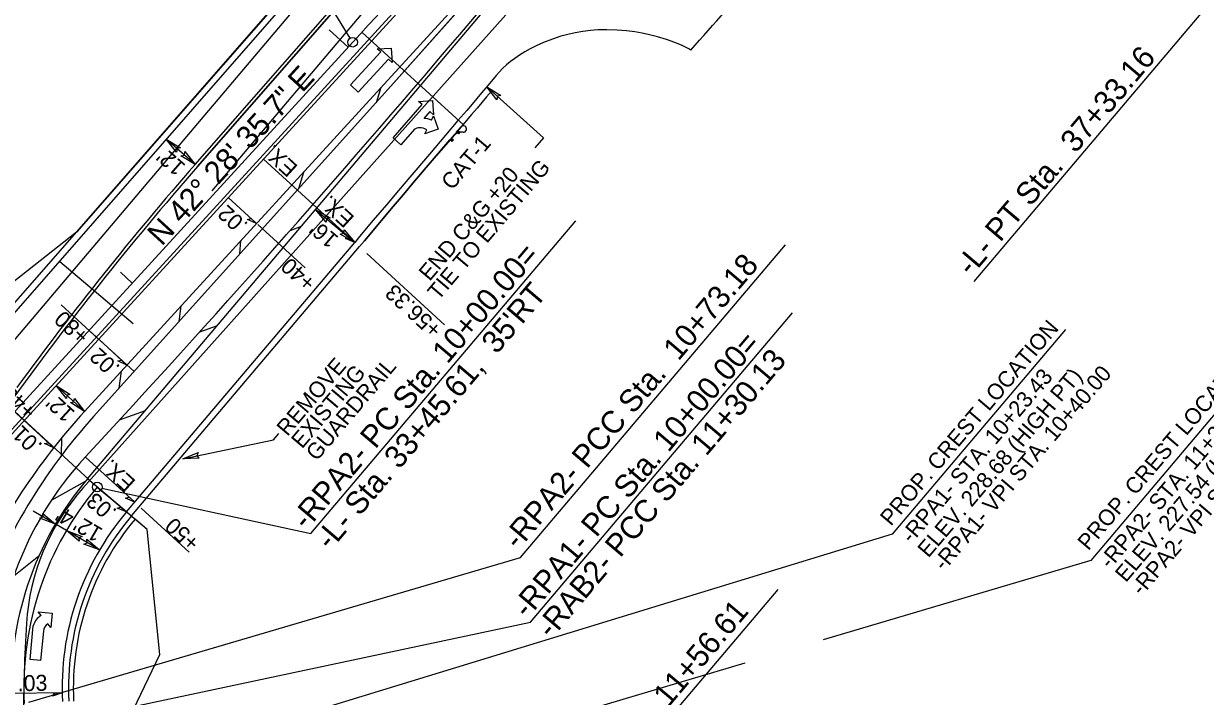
# Model space of a CAD drawing. Extents: x 1761082 to 1764358, y 421907 to 425434.
# Drawn here: x 1762805.2 to 1763174.6, y 423617.8 to 423828.1 of the extents above; entities that cross this region are included whole.
import ezdxf

# ---------------------------------------------------------------- set-up
doc = ezdxf.new("R2010")
doc.units = 0
for name, color, linetype in [('MARK HOOKS CENTER LEFT TURN ARROW CELL', 7, 'Continuous'), ('MARK HOOKS CENTER STRAIGHT LEFT TURN ARROW CELL', 7, 'Continuous'), ('MARK LEFT TURN ARROW CELL', 7, 'Continuous'), ('MARK STRAIGHT RIGHT ARROW CELL', 7, 'Continuous'), ('MARK UTURN ARROW CELL', 7, 'Continuous'), ('Prop Geotechnical Rock Plating', 7, 'Continuous'), ('Prop Horizontal Alignment Tick Large', 7, 'Continuous'), ('Prop Mkg 3ft Min Skp 3ft Wide White', 7, 'Continuous'), ('Prop Mkg 3ft Min Skp 9ft Wide White', 7, 'Continuous'), ('Prop Mkg Min Skp 6ft Yellow', 7, 'Continuous'), ('Prop Mkg Skp Wht', 7, 'Continuous'), ('Prop Mkg Solid White Diagonals', 7, 'Continuous'), ('Prop Mkg Solid White Edge Line', 7, 'Continuous'), ('Prop Mkg Solid White Lane Line', 7, 'Continuous'), ('Prop Mkg Solid White Multiple Diagonals V8i', 7, 'Continuous'), ('Prop Mkg Solid Yel Skip LT', 7, 'Continuous'), ('Prop Mkg Solid Yel Skip RT', 7, 'Continuous'), ('Prop Mkg Solid Yellow Diagonals', 7, 'Continuous'), ('Prop Mkg Solid Yellow Lane Line', 7, 'Continuous'), ('Prop Mkg Yld Lin', 7, 'Continuous'), ('Scratch_Level_0', 7, 'Continuous'), ('Scratch_Level_1', 7, 'Continuous'), ('Scratch_Level_5', 7, 'Continuous')]:
    doc.layers.add(name, color=color, linetype=linetype)

msp = doc.modelspace()

# ---------------------------------------------------------------- linework, layer by layer
at = {"layer": 'MARK HOOKS CENTER STRAIGHT LEFT TURN ARROW CELL'}
msp.add_line((1762839.12, 423747.01), (1762835.44, 423750.39), dxfattribs=at)
at = {"layer": 'MARK LEFT TURN ARROW CELL'}
for p, q in [((1762783.77, 423719.57), (1762897.35, 423849.4)), ((1762951.44, 423807.05), (1762949.96, 423808.4)), ((1762838.89, 423674.21), (1762910.22, 423758.4))]:
    msp.add_line(p, q, dxfattribs=at)
msp.add_lwpolyline([(1762951.44, 423807.05), (1762949.87, 423805.19), (1762948.4, 423803.44), (1762946.93, 423801.7), (1762945.23, 423799.7), (1762942.5, 423796.49), (1762938.59, 423791.92), (1762933.56, 423786.04), (1762927.4, 423778.84), (1762923.9, 423774.7), (1762920.11, 423770.21), (1762916.03, 423765.34), (1762911.78, 423760.26), (1762910.22, 423758.4)], dxfattribs=at)
msp.add_arc((1762902.22, 423620.56), 83, 139.7301, 182.9577, dxfattribs=at)
at = {"layer": 'MARK STRAIGHT RIGHT ARROW CELL'}
msp.add_line((1762908.06, 423822.3), (1762796.93, 423700.93), dxfattribs=at)
for centre, radius, start, end in [((1758482.74, 427874.03), 6000, 317.523415, 319.730103), ((1762902.22, 423620.56), 97, 139.7301, 182.9577)]:
    msp.add_arc(centre, radius, start, end, dxfattribs=at)
at = {"layer": 'MARK UTURN ARROW CELL'}
for points in [[(1762907.27, 423823.58), (1762843.21, 423928.07), (1762914.03, 424011.67)], [(1763061.63, 423994.46), (1763173.2, 423831.29), (1763102.23, 423747.51)], [(1762829.68, 423682.94), (1762895, 423668.7), (1762977.8, 423766.44)], [(1762806.79, 423615.98), (1762960.53, 423661.22), (1763043.33, 423758.96)], [(1762782.05, 423602.47), (1762963.66, 423641.02), (1763045.54, 423737.66)], [(1762831.94, 423537.15), (1762958.32, 423553.44), (1763041.12, 423651.17)]]:
    msp.add_lwpolyline(points, dxfattribs=at)
for centre in [(1762908.06, 423822.3), (1762828.21, 423683.26)]:
    msp.add_circle(centre, 1.5, dxfattribs=at)
at = {"layer": 'Prop Geotechnical Rock Plating'}
msp.add_line((1762843.83, 423670.03), (1762840.04, 423673.24), dxfattribs=at)
msp.add_lwpolyline([(1762852.54, 423557.42), (1762830, 423593.66), (1762847.81, 423630.88), (1762843.83, 423670.03)], dxfattribs=at)
msp.add_arc((1762902.22, 423620.56), 81.5, 139.7301, 182.9577, dxfattribs=at)
at = {"layer": 'Prop Horizontal Alignment Tick Large'}
for p, q in [((1762906.65, 423820.76), (1762900.75, 423826.17)), ((1762828.21, 423683.26), (1762834.32, 423678.09))]:
    msp.add_line(p, q, dxfattribs=at)
at = {"layer": 'Prop Mkg 3ft Min Skp 3ft Wide White'}
msp.add_line((1762796.93, 423700.93), (1762908.06, 423822.3), dxfattribs=at)
for centre, radius, start, end in [((1758482.74, 427874.03), 6000, 317.523415, 319.730103), ((1762902.22, 423620.56), 97, 139.7301, 182.9577)]:
    msp.add_arc(centre, radius, start, end, dxfattribs=at)
at = {"layer": 'Prop Mkg 3ft Min Skp 9ft Wide White'}
for p, q in [((1762897.35, 423849.4), (1762821.72, 423762.95)), ((1762821.72, 423762.95), (1762765.85, 423719.03)), ((1762838.89, 423674.21), (1762910.21, 423758.4))]:
    msp.add_line(p, q, dxfattribs=at)
msp.add_lwpolyline([(1762910.22, 423758.41), (1762911.78, 423760.26), (1762916.03, 423765.34), (1762920.11, 423770.21), (1762923.9, 423774.7), (1762927.4, 423778.84), (1762933.56, 423786.04), (1762938.48, 423791.8)], dxfattribs=at)
msp.add_arc((1762902.22, 423620.56), 83, 139.7301, 182.9577, dxfattribs=at)
at = {"layer": 'Prop Mkg Skp Wht'}
for p, q in [((1762785.28, 423718.25), (1762898.9, 423848.13)), ((1762837.37, 423675.5), (1762908.69, 423759.69))]:
    msp.add_line(p, q, dxfattribs=at)
msp.add_lwpolyline([(1763013.76, 423819.86), (1763013.17, 423820.21), (1763011.04, 423821.27), (1763008.75, 423822.22), (1763006.17, 423823.13), (1763003.38, 423823.97), (1763000.85, 423824.64), (1762998.6, 423825.13), (1762996.23, 423825.54), (1762993.64, 423825.86), (1762990.71, 423826.08), (1762987.53, 423826.18), (1762984.74, 423826.13), (1762982.39, 423825.92), (1762980.02, 423825.62), (1762977.58, 423825.22), (1762975.29, 423824.74), (1762973.11, 423824.15), (1762970.56, 423823.29), (1762967.71, 423822.18), (1762965.37, 423821.16), (1762963.58, 423820.25), (1762961.88, 423819.29), (1762960.22, 423818.26), (1762958.72, 423817.26), (1762957.39, 423816.27), (1762956.16, 423815.27), (1762954.9, 423814.1), (1762952.96, 423811.95), (1762950.4, 423808.93), (1762948.34, 423806.48), (1762946.87, 423804.73), (1762945.4, 423802.99), (1762943.71, 423801), (1762940.97, 423797.79), (1762937.07, 423793.22), (1762932.04, 423787.34), (1762925.88, 423780.14), (1762922.37, 423776), (1762918.58, 423771.49), (1762914.5, 423766.63), (1762910.24, 423761.55), (1762908.69, 423759.69)], dxfattribs=at)
for centre, radius, start, end in [((1758482.74, 427874.03), 6080, 318.179172, 318.487231), ((1762902.22, 423620.56), 85, 139.7301, 182.9577)]:
    msp.add_arc(centre, radius, start, end, dxfattribs=at)
at = {"layer": 'Prop Mkg Solid White Diagonals'}
for p, q in [((1763090.51, 424047.41), (1762859.56, 423783.42)), ((1762783.48, 423681.64), (1763081.76, 424007.42)), ((1762974.97, 423870.42), (1762920.01, 423808.54)), ((1762941.52, 423824.75), (1762977.99, 423867.8)), ((1762920.01, 423808.54), (1762827.08, 423705.32))]:
    msp.add_line(p, q, dxfattribs=at)
for centre, radius, start, end in [((1759889.49, 426410.3), 4000, 317.20084, 319.7301), ((1763611.44, 423125.64), 999, 138.81963, 144.27858), ((1762960.85, 423584.88), 180, 138.0009, 160.0358), ((1762902.22, 423620.56), 106, 137.2008, 182.9577)]:
    msp.add_arc(centre, radius, start, end, dxfattribs=at)
at = {"layer": 'Prop Mkg Solid White Edge Line'}
msp.add_line((1762864.1, 423775.9), (1762984.04, 423917.48), dxfattribs=at)
at = {"layer": 'Prop Mkg Solid White Lane Line'}
for p, q in [((1762859.56, 423783.42), (1763090.51, 424047.41)), ((1762783.48, 423681.64), (1763081.76, 424007.42)), ((1762920.01, 423808.54), (1762974.97, 423870.42)), ((1762941.52, 423824.75), (1762977.99, 423867.8)), ((1762827.08, 423705.32), (1762920.01, 423808.54))]:
    msp.add_line(p, q, dxfattribs=at)
for centre, radius, start, end in [((1759889.49, 426410.3), 4000, 317.20084, 319.7301), ((1763611.44, 423125.64), 999, 138.81963, 144.27858), ((1762960.85, 423584.88), 180, 138.0009, 160.0358), ((1762902.22, 423620.56), 106, 137.2008, 182.9577)]:
    msp.add_arc(centre, radius, start, end, dxfattribs=at)
at = {"layer": 'Prop Mkg Solid White Multiple Diagonals V8i'}
for p, q in [((1762816.51, 423753.76), (1762839.4, 423734.37)), ((1762839.71, 423719.36), (1762825.62, 423732.26)), ((1762828.21, 423683.26), (1762802.4, 423706.9)), ((1762843.83, 423670.03), (1762828.21, 423683.26))]:
    msp.add_line(p, q, dxfattribs=at)
at = {"layer": 'Prop Mkg Solid Yel Skip RT'}
for p, q in [((1762858.8, 423784.07), (1762849.77, 423791.98)), ((1762896.48, 423770.03), (1762908.69, 423759.69)), ((1762878.4, 423765.29), (1762893.16, 423751.77)), ((1762936.74, 423734), (1762912.47, 423756.23)), ((1762816.89, 423740.25), (1762828.5, 423729.62)), ((1762789.35, 423718.63), (1762805.32, 423704.01)), ((1762815.37, 423714.98), (1762824.22, 423706.88)), ((1762818.56, 423669.65), (1762808.21, 423675.72)), ((1762856.95, 423662.9), (1762841.96, 423676.62)), ((1762828.91, 423663.57), (1762818.56, 423669.65))]:
    msp.add_line(p, q, dxfattribs=at)
for points in [[(1762949.96, 423808.4), (1762967.72, 423792.43), (1762965.05, 423789.27)], [(1762854.91, 423692.06), (1762883.31, 423697.99), (1762884.97, 423699.95)]]:
    msp.add_lwpolyline(points, dxfattribs=at)
at = {"layer": 'Prop Mkg Solid Yellow Diagonals'}
for p, q in [((1762915.73, 423820.26), (1762920.14, 423820.48)), ((1762916.83, 423819.25), (1762915.73, 423820.26)), ((1762920.14, 423820.48), (1762920.37, 423816)), ((1762907.36, 423808.94), (1762916.83, 423819.25)), ((1762919.26, 423817.02), (1762909.79, 423806.71)), ((1762920.37, 423816), (1762919.26, 423817.02)), ((1762909.79, 423806.71), (1762907.36, 423808.94)), ((1762920.67, 423792.39), (1762929.73, 423802.8)), ((1762928.6, 423803.78), (1762933.01, 423804.06)), ((1762929.73, 423802.8), (1762928.6, 423803.78)), ((1762933.01, 423804.06), (1762933.35, 423799.65)), ((1762932.22, 423800.63), (1762930.35, 423798.48)), ((1762933.35, 423799.65), (1762932.22, 423800.63)), ((1762932.66, 423797.94), (1762933.31, 423799.29)), ((1762933.31, 423799.29), (1762934.77, 423795.11)), ((1762927.4, 423795.09), (1762923.16, 423790.22)), ((1762934.77, 423795.11), (1762930.58, 423793.64)), ((1762930.58, 423793.64), (1762931.2, 423794.96)), ((1762923.16, 423790.22), (1762920.67, 423792.39)), ((1762810.65, 423643.1), (1762809.71, 423644.24)), ((1762809.71, 423644.24), (1762814.09, 423643.86)), ((1762814.09, 423643.86), (1762813.7, 423639.38)), ((1762807.18, 423629.37), (1762808.22, 423639.87)), ((1762813.7, 423639.38), (1762812.75, 423640.52)), ((1762811.36, 423638.15), (1762810.46, 423629.05)), ((1762810.46, 423629.05), (1762807.18, 423629.37))]:
    msp.add_line(p, q, dxfattribs=at)
for centre, radius, start, end in [((1762930.47, 423794.06), 4.43, 60.5808, 91.4594), ((1762928.82, 423793), 2.52, 88.0631, 124.3751), ((1762929.03, 423791.09), 4.43, 60.6996, 91.5532), ((1762813.29, 423638.57), 5.25, 120.3493, 165.661), ((1762814.61, 423637.84), 3.27, 124.6789, 174.3371)]:
    msp.add_arc(centre, radius, start, end, dxfattribs=at)
at = {"layer": 'Prop Mkg Solid Yellow Lane Line'}
for points in [[(1762953.16, 423804.33), (1762949.96, 423808.4), (1762954.38, 423805.64), (1762953.29, 423805.4)], [(1762853.03, 423787.95), (1762849.77, 423791.98), (1762854.23, 423789.28), (1762853.14, 423789.03)], [(1762855.54, 423788.1), (1762858.8, 423784.07), (1762854.34, 423786.77), (1762855.43, 423787.02)], [(1762899.81, 423766.06), (1762896.48, 423770.03), (1762900.98, 423767.41), (1762899.9, 423767.14)], [(1762905.36, 423763.66), (1762908.69, 423759.69), (1762904.19, 423762.32), (1762905.27, 423762.59)], [(1762818.54, 423710.88), (1762815.37, 423714.98), (1762819.76, 423712.18), (1762818.67, 423711.95)], [(1762821.05, 423710.97), (1762824.22, 423706.88), (1762819.82, 423709.67), (1762820.91, 423709.9)], [(1762860.08, 423692.25), (1762854.91, 423692.06), (1762859.75, 423694), (1762859.29, 423692.98)], [(1762811.15, 423675.01), (1762815.11, 423671.67), (1762810.23, 423673.49), (1762811.25, 423673.94)], [(1762822.52, 423666.31), (1762818.56, 423669.65), (1762823.45, 423667.83), (1762822.42, 423667.38)], [(1762824.95, 423666.91), (1762828.91, 423663.57), (1762824.03, 423665.39), (1762825.05, 423665.84)]]:
    msp.add_lwpolyline(points, close=True, dxfattribs=at)
at = {"layer": 'Prop Mkg Yld Lin'}
for p, q in [((1762938.48, 423791.8), (1762940.78, 423794.49)), ((1762941.03, 423794.16), (1762939.49, 423792.98)), ((1762940.5, 423794.16), (1762940.95, 423794.69)), ((1762940.5, 423794.16), (1762941.57, 423794.17)), ((1762941.11, 423793.64), (1762940.5, 423794.16)), ((1762940.78, 423794.49), (1762941.9, 423795.8)), ((1762940.87, 423794.59), (1762940.78, 423794.49)), ((1762940.95, 423794.69), (1762941.57, 423794.17)), ((1762940.95, 423794.69), (1762941.11, 423793.64)), ((1762941.57, 423794.17), (1762941.11, 423793.64)), ((1762942.59, 423794.16), (1762941.49, 423794.23)), ((1762938.48, 423791.8), (1762938.93, 423792.33)), ((1762939.09, 423791.27), (1762938.48, 423791.8)), ((1762938.48, 423791.8), (1762939.55, 423791.8)), ((1762938.93, 423792.33), (1762939.55, 423791.8)), ((1762938.93, 423792.33), (1762939.09, 423791.27)), ((1762939.55, 423791.8), (1762939.09, 423791.27))]:
    msp.add_line(p, q, dxfattribs=at)
msp.add_ellipse((1762942.65, 423795.15), major_axis=(-0.755, 0.645), ratio=0.995379, start_param=2.210226, end_param=6.283185, dxfattribs=at)
at = {"layer": 'Scratch_Level_0'}
for p, q in [((1762858.8, 423784.07), (1763100.11, 424059.9)), ((1762790.28, 423687.58), (1763082.58, 424006.83)), ((1762824.22, 423706.88), (1762975.24, 423871.83)), ((1762825.16, 423685.85), (1762978.75, 423867.15)), ((1762942.65, 423796.45), (1762910.94, 423825.44)), ((1762915.47, 423803.5), (1762917.01, 423808.22)), ((1762891.19, 423776.54), (1762892.75, 423781.73)), ((1762888.56, 423763.5), (1762892.03, 423764.78)), ((1762872.82, 423756.12), (1762873.14, 423760.31)), ((1762853.84, 423735.05), (1762854.47, 423739.91)), ((1762860.23, 423731.74), (1762865.77, 423733.78)), ((1762835.04, 423714.17), (1762835.79, 423719.51)), ((1762835.21, 423704.25), (1762843.27, 423707.23)), ((1762816.99, 423693.07), (1762817.13, 423698.71)), ((1762813.89, 423679.15), (1762824.51, 423685.07)), ((1762802.16, 423655.53), (1762809.99, 423661.73))]:
    msp.add_line(p, q, dxfattribs=at)
for centre, radius, start, end in [((1763611.44, 423125.64), 1000, 138.81963, 143.93371), ((1762971.73, 423571.82), 200, 137.5234, 155.8731), ((1762902.22, 423620.56), 101, 139.7301, 182.9577)]:
    msp.add_arc(centre, radius, start, end, dxfattribs=at)
at = {"layer": 'Scratch_Level_1'}
for p, q in [((1762785.64, 423709.58), (1762903.23, 423848.39)), ((1762823.74, 423682.91), (1762959.47, 423834.79)), ((1763030.64, 423628.18), (1762887.46, 423585.7))]:
    msp.add_line(p, q, dxfattribs=at)
for points in [[(1763130.9, 423732.48), (1763076.67, 423668.47), (1762885.38, 423609.96)], [(1763192.02, 423723.1), (1763138.79, 423660.27), (1763055.17, 423635.46)]]:
    msp.add_lwpolyline(points, dxfattribs=at)
for centre in [(1762831.58, 423691.68), (1762831.58, 423691.68), (1762823.74, 423682.91), (1762823.74, 423682.91), (1762806.07, 423640.59), (1762806.07, 423640.59)]:
    msp.add_circle(centre, 0.0417, dxfattribs=at)
for centre, radius, start, end in [((1762875.94, 423636.26), 70, 138.2154, 176.4538), ((1763305.11, 423609.67), 500, 176.4538, 179.9158)]:
    msp.add_arc(centre, radius, start, end, dxfattribs=at)
at = {"layer": 'Scratch_Level_5'}
for p, q in [((1762880.19, 423785.78), (1762908.69, 423759.69)), ((1762869.16, 423773.74), (1762878.02, 423765.64)), ((1762828.65, 423729.49), (1762837.5, 423721.38)), ((1762805.32, 423704.01), (1762814.58, 423695.53)), ((1762839.91, 423678.5), (1762824.49, 423692.62)), ((1762837.37, 423675.5), (1762825.16, 423685.85)), ((1762817.24, 423618.96), (1762801.24, 423618.66))]:
    msp.add_line(p, q, dxfattribs=at)
for points in [[(1762878.02, 423765.64), (1762875.13, 423766.92), (1762876.31, 423767.2)], [(1762908.69, 423759.69), (1762905.8, 423760.98), (1762906.98, 423761.25)], [(1762837.5, 423721.38), (1762834.61, 423722.67), (1762835.79, 423722.94)], [(1762814.58, 423695.53), (1762811.69, 423696.82), (1762812.88, 423697.09)], [(1762839.91, 423678.5), (1762837.02, 423679.79), (1762838.2, 423680.06)], [(1762837.37, 423675.5), (1762834.43, 423676.68), (1762835.6, 423677)], [(1762817.24, 423618.96), (1762814.26, 423617.91), (1762814.93, 423618.92)]]:
    msp.add_lwpolyline(points, close=True, dxfattribs=at)

# ---------------------------------------------------------------- texts
at = {"layer": 'MARK HOOKS CENTER LEFT TURN ARROW CELL'}
msp.add_text('N 42%%d 28\' 35.7" E', height=7, rotation=47.5234, dxfattribs=at).set_placement((1762848.4, 423758.31))
at = {"layer": 'MARK UTURN ARROW CELL'}
for s, p in [('-L- PT Sta.  37+33.16', (1763101.42, 423748.84)), ('-RPA2- PC Sta. 10+00.00=', (1762893.63, 423669.49)), ('-RPA2- PCC Sta.  10+73.18', (1762959.8, 423663.31)), ("-L- Sta. 33+45.61,  35'RT", (1762901.1, 423663.16)), ('-RPA1- PC Sta. 10+00.00=', (1762962.69, 423641.84)), ('-RAB2- PCC Sta. 11+30.13', (1762970.16, 423635.51)), ('-RPA2- PRC Sta.  11+56.61', (1762956.69, 423555.09))]:
    msp.add_text(s, height=7, rotation=49.7301, dxfattribs=at).set_placement(p)
at = {"layer": 'Prop Mkg Min Skp 6ft Yellow'}
for s, rotation, p in [('EX.', 137.5234, (1762891.21, 423783.45)), ('.02', 137.5234, (1762875.66, 423765.5)), ('EX.', 137.5234, (1762908.91, 423767.59)), ('.02', 137.5234, (1762835.62, 423720.87)), ('.01', 136.2121, (1762811.35, 423696.45)), ('EX.', 137.5234, (1762840.51, 423685.05)), ('.03', 139.7301, (1762834.65, 423675.88)), ('.03', 1.0776, (1762803.37, 423619.41))]:
    msp.add_text(s, height=5, rotation=rotation, dxfattribs=at).set_placement(p)
at = {"layer": 'Prop Mkg Solid Yel Skip LT'}
for s, rotation, p in [("12'", 138.8196, (1762856.12, 423783.83)), ('END C&G +20', 49.7301, (1762932.1, 423747.35)), ('TIE TO EXISTING', 49.7301, (1762934.86, 423741.33)), ("16'", 139.7301, (1762903.95, 423761.27)), ('+56.33', 137.5234, (1762936.34, 423733.06)), ('REMOVE', 49.7301, (1762887.66, 423698.87)), ('EXISTING', 49.7301, (1762892.23, 423694.99)), ('GUARDRAIL', 49.7301, (1762896.81, 423691.11)), ("12'", 137.5234, (1762821.53, 423706.7)), ("4'", 149.5992, (1762821.51, 423674.92)), ("12'", 149.5992, (1762830.3, 423670))]:
    msp.add_text(s, height=5, rotation=rotation, dxfattribs=at).set_placement(p)
at = {"layer": 'Prop Mkg Solid Yel Skip RT'}
for s, p in [('+40', (1762896.9, 423747.66)), ('+80', (1762826.07, 423731.1)), ('+45.46', (1762809.49, 423707.49)), ('+50', (1762860.65, 423666.43))]:
    msp.add_text(s, height=5, rotation=137.5234, dxfattribs=at).set_placement(p)
at = {"layer": 'Prop Mkg Yld Lin'}
msp.add_text('CAT-1', height=5, rotation=49.7301, dxfattribs=at).set_placement((1762939.11, 423775.78))
at = {"layer": 'Scratch_Level_1'}
for s, p in [('PROP. CREST LOCATION', (1763076.32, 423670.81)), ('PROP. CREST LOCATION', (1763138.04, 423663.14)), ('-RPA1- STA. 10+23.43', (1763082.75, 423665.36)), ('ELEV. 228.68 (HIGH PT)', (1763088.02, 423660.89)), ('-RPA1- VPI STA. 10+40.00', (1763092.92, 423656.74)), ('-RPA2- VPI STA. 11+14.00', (1763154.73, 423648.99)), ('-RPA2- STA. 11+25.54', (1763144.83, 423657.39)), ('ELEV. 227.54 (HIGH PT)', (1763149.77, 423653.2))]:
    msp.add_text(s, height=5, rotation=49.5644, dxfattribs=at).set_placement(p)

doc.saveas('drawing.dxf')
